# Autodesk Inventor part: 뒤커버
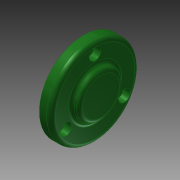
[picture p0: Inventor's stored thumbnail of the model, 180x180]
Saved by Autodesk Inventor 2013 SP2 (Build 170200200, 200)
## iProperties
Created: 2015-11
Part Number: 뒤커버
Material: 알루미늄 6061
Document SubType Name: Modeling
Designer: mduedu
Density: 1 g/cm^3
Author: mduedu
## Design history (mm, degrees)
sketch "스케치5"
  geometry: C1 r 30 at (0, 0); 2 further points
  constraints: 2 coincident, 1 centre point
  dimensions: "d66" = 60 diameter of C1
extrude "돌출2" new body sketch "스케치5" distance "d67" = 8; taper "d68" = 0 deg
sketch "스케치8"
  geometry: C1 r 16.5 at (0, 0); 1 further point
  constraints: 1 centre point, 1 coincident
  dimensions: "d98" = 33 diameter of C1
extrude "돌출4" join sketch "스케치8" distance "d99" = 4; taper "d100" = -30 deg
sketch "스케치6"
  geometry: C1 r 16 at (0, 0); 1 further point
  constraints: 1 centre point, 1 coincident
  dimensions: "d69" = 32 diameter of C1
extrude "돌출3" join sketch "스케치6" distance "d70" = 3; taper "d71" = 0 deg
hole "구멍5" diameter "d74" = 25; stored, may be unused: countersink angle "d78" = 90 deg, drill point angle "d80" = 0 deg; dims "d72" = 10, "d73" = 10, "d75" = 6, "d76" = 4, "d77" = 2, "d79" = 10
fillet "모깎기8" dims "d82" = 3
fillet "모깎기9" dims "d83" = 3
fillet "모깎기10" dims "d84" = 0.3
sketch "스케치7" dims "d85" = 46
  geometry: 3 further points
  constraints: 2 vertical alignment, 1 coincident, 2 other
hole "구멍6" sketch "스케치7" at (0, 23) diameter "d86" = 4.5; stored, may be unused: countersink angle "d90" = 90 deg, drill point angle "d92" = 0 deg; dims "d87" = 6, "d88" = 8, "d89" = 4.6, "d91" = 10
chamfer "모따기2" distance "d102" = 1; stored, may be unused: second distance "d103" = 2, angle "d104" = 45 deg
node "솔리드2"
pattern_circular "원형 패턴3" dims angle "d94" = 360 deg
